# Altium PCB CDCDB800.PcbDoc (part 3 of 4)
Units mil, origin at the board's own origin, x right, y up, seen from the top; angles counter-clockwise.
Board outline 4100 x 4100 mil, 4 copper layers (Layer 1 - Top Layer, Layer 2 - GND, Layer 3 - PWR, Layer 4 - Bottom Layer), stack 61.2 mil thick; 245 components, 143 nets, 740 pads, 720 vias.
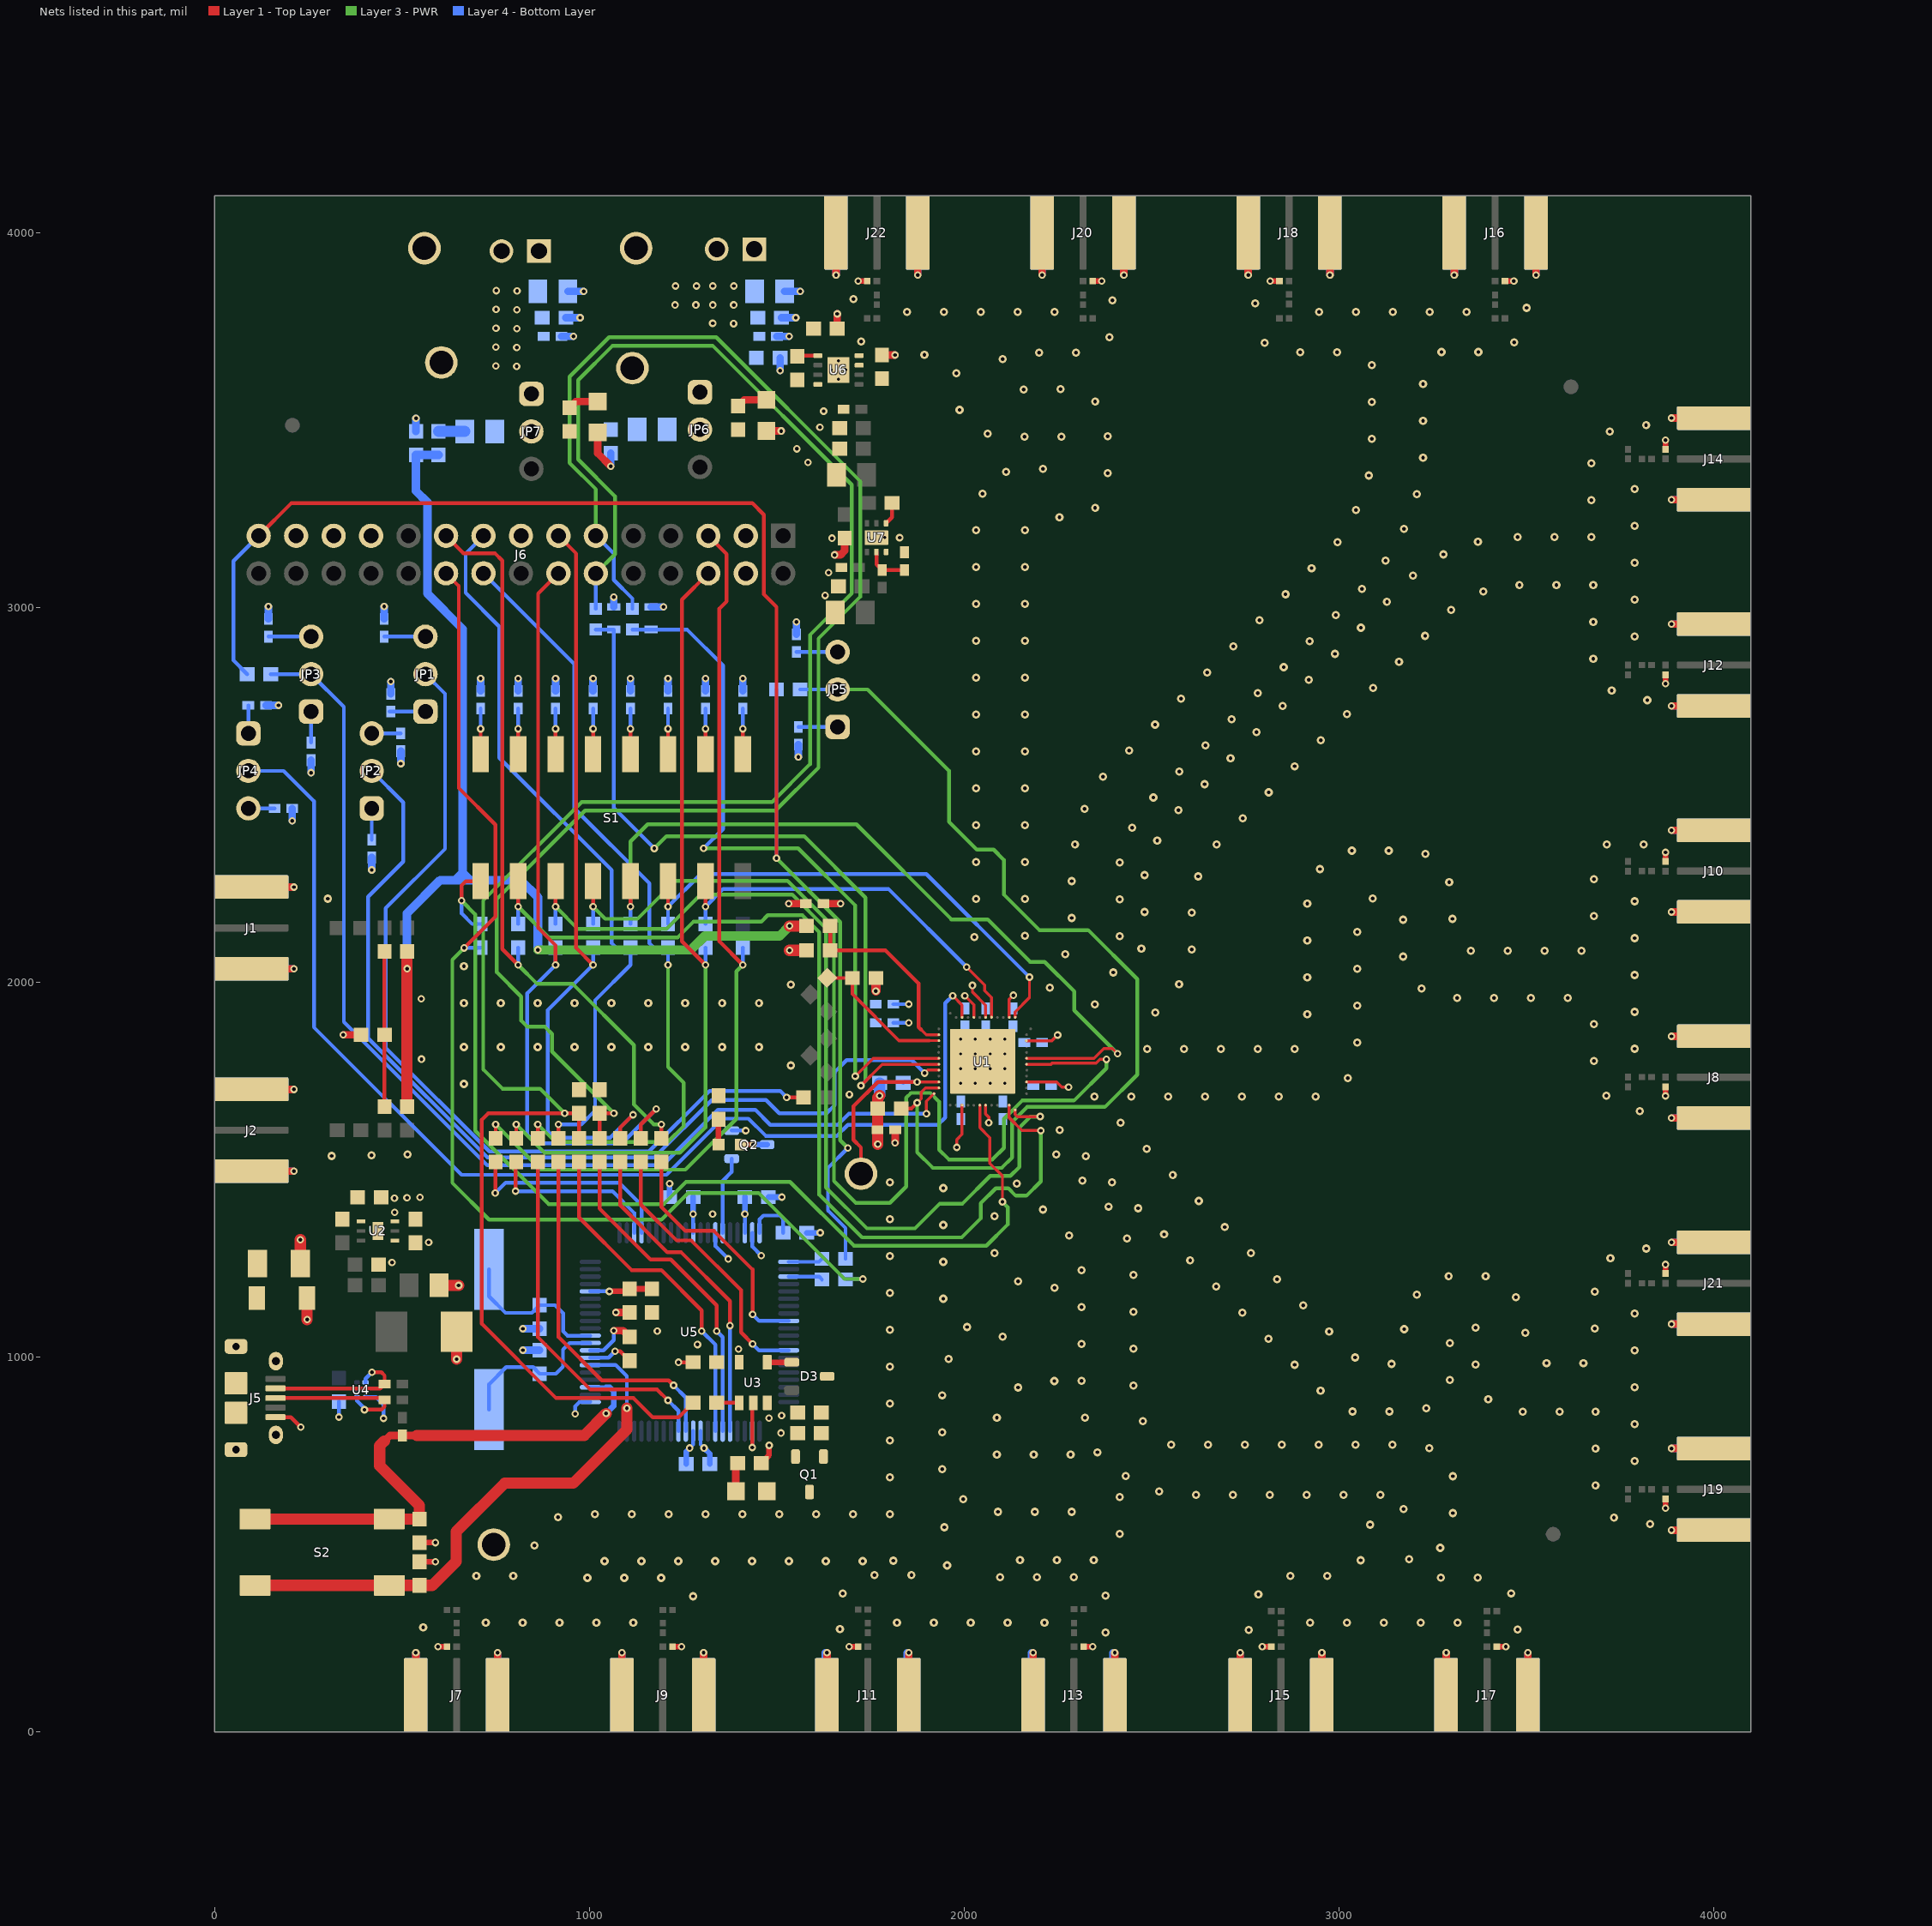
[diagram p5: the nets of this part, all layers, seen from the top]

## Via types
v1: diameter 22, hole 10, Layer 1 - Top Layer to Layer 4 - Bottom Layer, tented top, 430 vias
v2: diameter 20, hole 10, Layer 1 - Top Layer to Layer 4 - Bottom Layer, tented top, 268 vias
v3: diameter 19.68, hole 7.87, Layer 1 - Top Layer to Layer 4 - Bottom Layer, 22 vias

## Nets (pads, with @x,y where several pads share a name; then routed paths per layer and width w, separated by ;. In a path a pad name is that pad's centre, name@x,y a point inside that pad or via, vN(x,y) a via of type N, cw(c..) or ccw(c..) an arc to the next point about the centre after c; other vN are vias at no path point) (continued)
GND: C1.2 C2.2 C3.2 C4.2 C5.2 C6.2 C7.2 C8.2 C9.2 C10.2 C11.2 C12.2 C13.2 C14.2 C15.2 C16.2 C17.2 C18.2 C19.2 C20.2 C21.1 C22.2 C23.2 C24.1 C25.2 C26.2 C27.2 C28.2 C29.2 C30.2 C31.2 C32.2 C33.2 C34.2 C35.2 C36.2 C37.2 C38.2 C39.2 C40.2 C41.2 C42.2 C43.2 C44.2 C45.2 C46.2 C47.2 C48.2 D1.2 D5.2 D6.2 J1.2 J1.3 J1.4 J1.5 J2.2 J2.3 J2.4 J2.5 J3.2 J4.2 J5.5 J6.3 J6.4 J6.15 J6.23 J6.25 J6.27 J7.2 J7.3 J7.4 J7.5 J8.2 J8.3 J8.4 J8.5 J9.2 J9.3 J9.4 J9.5 J10.2 J10.3 J10.4 J10.5 J11.2 J11.3 J11.4 J11.5 J12.2 J12.3 J12.4 J12.5 J13.2 J13.3 J13.4 J13.5 J14.2 J14.3 J14.4 J14.5 J15.2 J15.3 J15.4 J15.5 J16.2 J16.3 J16.4 J16.5 J17.2 J17.3 J17.4 J17.5 J18.2 J18.3 J18.4 J18.5 J19.2 J19.3 J19.4 J19.5 J20.2 J20.3 J20.4 J20.5 J21.2 J21.3 J21.4 J21.5 J22.2 J22.3 J22.4 J22.5 Q1.2 Q2.2 R4.1 R5.1 R13.1 R26.1 R28.2 R29.2 R34.2 R55.1 R56.1 R57.2 R77.1 R78.1 R81.2 R82.2 R89.1 R90.1 R93.2 R94.2 R101.1 R102.1 R104.2 R106.2 R113.1 R114.1 R117.2 R118.2 R125.1 TP4.1 TP6.1 U1.49 U2.3 U2.7 U3.3 U4.3 U5.14 U5.19 U5.49 U5.61 U5.68 U6.4 U6.9 U7.3 U7.7@1766.5,3187.61 | length 10933.4
  Layer 1 - Top Layer w10.1: J5.5@162.4,840.04 203.66,840.04 v2(230.1,813.6) ; v2(1237.93,986.73) C19.2@1277.01,986.73
  Layer 1 - Top Layer w15: C22.2@546.78,454.16 v2(589.26,454.16) ; R55.1@546.78,505.34 v2(589.26,505.34) ; v2(596,227.6) R77.1@620.05,227.6 ; R81.2@1222.02,227.6 v2(1246.08,227.6) ; v2(1693.46,227.6) R89.1@1717.52,227.6 ; v2(1717.56,3872.4) R118.2@1741.61,3872.4 ; R93.2@2319.49,227.6 v2(2343.54,227.6) ; R114.1@2343.58,3872.4 v2(2367.64,3872.4) ; v2(2796,227.6) R101.1@2820.05,227.6 ; v2(2817.56,3872.4) R106.2@2841.61,3872.4 ; R104.2@3422.02,227.6 v2(3446.08,227.6) ; R102.1@3443.58,3872.4 v2(3467.64,3872.4) ; v2(3872.4,597.56) R113.1@3872.4,621.61 ; R117.2@3872.4,1223.58 v2(3872.4,1247.64) ; v2(3872.4,1697.56) R78.1@3872.4,1721.61 ; R82.2@3872.4,2323.58 v2(3872.4,2347.64) ; v2(3872.4,2797.56) R90.1@3872.4,2821.61 ; R94.2@3872.4,3423.58 v2(3872.4,3447.64)
  Layer 1 - Top Layer w20: J2.2@98.42,1496.79 v2(211.85,1496.79) ; J2.3@98.42,1714.9 v2(211.85,1714.9) ; J1.2@98.42,2036.79 v2(211.85,2036.79) ; J1.3@98.42,2254.9 v2(211.85,2254.9) ; v2(343.5,1860.85) R13.1@390.51,1860.85 ; J7.3@536.98,98.43 v2(536.98,211.85) ; J7.2@755.09,98.43 v2(755.09,211.85) ; D5.2@1022.4,3468.01 1022.4,3412.81 v2(1057.4,3377.81) ; v2(1065.3,1071.1) 1090.4,1071.1 C28.2@1107.4,1054.09 ; v2(1070.79,1119.61) C27.2@1107.4,1119.61 ; J9.3@1086.98,98.43 v2(1086.98,211.85) ; J9.2@1305.09,98.43 v2(1305.09,211.85) ; D6.2@1472.4,3472.56 v2@1512.09,3472.56 ; C15.2@1625.12,2211.02 v2(1670.74,2211.02) ; J11.3@1634.45,98.43 v2(1634.45,211.85) ; v2(1654.4,3141.5) 1670.6,3141.5 1681.5,3152.4 C42.2@1681.5,3186.11 ; v2(1658.54,3888.15) J22.2@1658.54,4001.57 ; C33.2@1661.5,3745 v2@1661.5,3784.69 ; C38.2@1781,3675 v2(1816,3675) ; v2@1816.5,1572.6 C12.2@1816.5,1607.13 ; J11.2@1852.56,98.43 v2(1852.56,211.85) ; v2(1876.65,3888.15) J22.3@1876.65,4001.57 ; J13.3@2184.45,98.43 v2(2184.45,211.85) ; v2(2208.54,3888.15) J20.2@2208.54,4001.57 ; J13.2@2402.56,98.43 v2(2402.56,211.85) ; v2(2426.65,3888.15) J20.3@2426.65,4001.57 ; J15.3@2736.98,98.43 v2(2736.98,211.85) ; v2(2758.54,3888.15) J18.2@2758.54,4001.57 ; J15.2@2955.09,98.43 v2(2955.09,211.85) ; v2(2976.65,3888.15) J18.3@2976.65,4001.57 ; J17.3@3286.98,98.43 v2(3286.98,211.85) ; v2(3308.54,3888.15) J16.2@3308.54,4001.57 ; J17.2@3505.09,98.43 v2(3505.09,211.85) ; v2(3526.65,3888.15) J16.3@3526.65,4001.57 ; v2(3888.15,538.54) J19.3@4001.57,538.54 ; v2(3888.15,756.65) J19.2@4001.57,756.65 ; v2(3888.15,1088.54) J21.3@4001.57,1088.54 ; v2(3888.15,1306.65) J21.2@4001.57,1306.65 ; v2(3888.15,1638.54) J8.3@4001.57,1638.54 ; v2(3888.15,1856.65) J8.2@4001.57,1856.65 ; v2(3888.15,2188.54) J10.3@4001.57,2188.54 ; v2(3888.15,2406.65) J10.2@4001.57,2406.65 ; v2(3888.15,2738.54) J12.3@4001.57,2738.54 ; v2(3888.15,2956.65) J12.2@4001.57,2956.65 ; v2(3888.15,3288.54) J14.3@4001.57,3288.54 ; v2(3888.15,3506.65) J14.2@4001.57,3506.65
  Layer 1 - Top Layer w30: R57.2@228.86,1250.36 v2(228.86,1313.76) ; v2(246.95,1100.85) C24.1@246.95,1158.44 ; C16.2@598.78,1192.11 v2@651.81,1192.11 ; v2@645.79,994.9 D1.2@645.79,1068.29 ; v2(1534.26,2086.02) R26.1@1579.88,2086.02
  Layer 4 - Bottom Layer w10.1: v2(331.78,840.38) C21.1@331.78,881.8 ; U4.3@403.59,893.61 431.19,893.61 450.6,874.2 v2(450.6,836.9) ; v2(962.1,849.1) 962.1,869.1 973.59,880.59 U5.61@1002.64,880.59 ; U5.68@1002.64,1018.39 1037.89,1018.39 1065.3,1045.8 v2(1065.3,1071.1) ; U5.49@1296.93,802.84 1296.93,767.25 v2(1306.3,757.87) ; U5.14@1336.3,1332.36 1336.3,1296.9 v2(1370.7,1262.5) ; Q2.2@1380.16,1605 v2(1417.4,1605) ; U5.19@1434.73,1332.36 1434.73,1295.77 v2(1459,1271.5) ; C11.2@1811.5,1892.53 v2(1852.73,1892.53) ; C10.2@1811.5,1942.53 v2(1852.73,1942.53)
  Layer 4 - Bottom Layer w15: C30.2@1214.41,1427.6 v2(1214.41,1463.41) ; v2(1306.3,757.87) 1321.5,742.68 C32.2@1321.5,715 ; C31.2@1478.03,1427.44 v2(1513.84,1427.44) ; C29.2@1580.39,1332.36 v2(1616.2,1332.36)
  Layer 4 - Bottom Layer w20: J2.4@98.42,1496.79 v2(211.85,1496.79) ; J2.5@98.42,1714.9 v2(211.85,1714.9) ; J1.4@98.42,2036.79 v2(211.85,2036.79) ; J1.5@98.42,2254.9 v2(211.85,2254.9) ; R28.2@143.5,2970.49 v2(143.5,3003.7) ; v2(207.24,2431.79) R29.2@207.24,2465 ; R4.1@452.6,2970.49 v2(452.6,3003.7) ; v2(496.89,2584.55) R5.1@496.89,2617.76 ; J7.5@536.98,98.43 v2(536.98,211.85) ; C9.2@537.4,3471.01 v2(537.4,3506.22) ; J7.4@755.09,98.43 v2(755.09,211.85) ; v2(822.8,1019.09) C25.2@867.4,1019.09 ; v2(822.8,1076.1) C26.2@867.4,1076.1 ; C48.2@925.5,3724.91 v2(957.91,3724.91) ; C47.2@937.38,3774.41 v2(975.59,3774.41) ; C46.2@942.88,3845.12 v2(984.88,3845.12) ; v2(1057.4,3377.81) C1.2@1057.4,3413.02 ; C14.2@1065,3002.44 v2(1065,3028.6) ; J9.5@1086.98,98.43 v2(1086.98,211.85) ; C13.2@1165,3002.44 v2(1198.21,3002.44) ; J9.4@1305.09,98.43 v2(1305.09,211.85) ; C41.2@1500.88,3724.91 v2(1533.29,3724.91) ; C40.2@1512.76,3774.41 v2(1550.97,3774.41) ; C39.2@1521.26,3845.12 v2(1563.26,3845.12) ; R34.2@1552.91,2929.65 v2(1552.91,2962.86) ; J11.5@1629.85,98.43 v2@1629.85,211.85 ; v2(1658.54,3888.15) J22.4@1658.54,4001.57 ; J11.4@1847.96,98.43 v2@1847.96,211.85 ; v2(1876.65,3888.15) J22.5@1876.65,4001.57 ; J13.5@2179.85,98.43 v2@2179.85,211.85 ; v2(2208.54,3888.15) J20.4@2208.54,4001.57 ; J13.4@2397.96,98.43 v2@2397.96,211.85 ; v2(2426.65,3888.15) J20.5@2426.65,4001.57 ; J15.5@2736.98,98.43 v2(2736.98,211.85) ; v2(2758.54,3888.15) J18.4@2758.54,4001.57 ; J15.4@2955.09,98.43 v2(2955.09,211.85) ; v2(2976.65,3888.15) J18.5@2976.65,4001.57 ; J17.5@3286.98,98.43 v2(3286.98,211.85) ; v2(3308.54,3888.15) J16.4@3308.54,4001.57 ; J17.4@3505.09,98.43 v2(3505.09,211.85) ; v2(3526.65,3888.15) J16.5@3526.65,4001.57 ; v2(3888.15,538.54) J19.5@4001.57,538.54 ; v2(3888.15,756.65) J19.4@4001.57,756.65 ; v2(3888.15,1088.54) J21.5@4001.57,1088.54 ; v2(3888.15,1306.65) J21.4@4001.57,1306.65 ; v2(3888.15,1638.54) J8.5@4001.57,1638.54 ; v2(3888.15,1856.65) J8.4@4001.57,1856.65 ; v2(3888.15,2188.54) J10.5@4001.57,2188.54 ; v2(3888.15,2406.65) J10.4@4001.57,2406.65 ; v2(3888.15,2738.54) J12.5@4001.57,2738.54 ; v2(3888.15,2956.65) J12.4@4001.57,2956.65 ; v2(3888.15,3288.54) J14.5@4001.57,3288.54 ; v2(3888.15,3506.65) J14.4@4001.57,3506.65
  other v1: 2378.13,265.65 2760.23,272.37 3477.62,273.05 1668.84,274.49 556.64,279.49 723.63,292.04 822.05,292.04 920.48,292.05 1018.9,292.05 1117.33,292.05 1821.09,292.04 1919.52,292.04 2017.94,292.05 2116.37,292.05 2214.79,292.05 2923.63,292.04 3022.05,292.04 3120.48,292.05 3218.9,292.05 3317.33,292.05 1277.01,362.19 2378.13,364.08 2785.71,367.44 1676.24,369.77 3460.53,369.98 994.92,411.4 1093.35,411.4 1191.77,411.4 3272.9,411.57 3371.33,411.58 2096.04,413.29 2194.46,413.29 2292.89,413.29 698.44,416.79 796.87,416.79 2870.95,416.66 2969.37,416.66 1761.48,418.98 1859.9,418.98 1954.97,444.46 1040.63,455.82 1139.05,455.83 1237.48,455.83 1335.9,455.83 1434.33,455.83 1532.75,455.83 1631.18,455.83 1729.6,455.83 1811.5,457.1 3058.57,458.25 2149.48,458.98 2247.9,458.98 2346.33,458.98 3187.66,460.79 3271.09,491.5 853.32,497.42 2415.93,528.58 1947.8,546.4 3084.05,553.33 3831.54,555.31 3734.61,572.4 916.59,572.82 1014.64,581.4 1113.06,581.4 1211.49,581.4 1309.91,581.4 1408.34,581.4 1506.76,581.4 1605.19,581.4 1703.61,581.4 1802.04,581.4 3304.76,583.99 2090.56,587.51 2188.98,587.51 2287.41,587.51 3173.25,594.92 1998.07,621.17 2415.92,627 2619.08,633.01 2717.51,633.01 2815.93,633.01 2914.36,633.01 3012.78,633.01 3111.21,633.01 2521.03,641.59 3685.39,657.64 1802.03,679.83 3304.76,682.42 2431.83,683.18 1941.61,701.8 3790.03,723.43 2087.85,740.47 2186.27,740.47 2284.7,740.47 2356.43,746.45 3685.39,756.06 3241.49,757.81 2552.89,766.39 2651.31,766.39 2749.74,766.39 2848.16,766.39 2946.59,766.39 3045.01,766.39 3143.44,766.39 1802.03,778.25 1941.61,800.22 3790.03,821.85 2477.49,829.66 2087.85,838.89 2322.76,838.94 3491.54,854.49 3589.97,854.49 3685.39,854.49 3036.95,855.26 3135.38,855.26 3233.43,863.84 1802.03,876.68 3399.05,888.15 1941.61,898.65 2951.71,910.47 2144.3,919.52 3790.03,920.27 2452.01,924.73 2241.23,936.61 2314.19,936.99 3296.69,939.24 1802.03,975.1 2882.12,980.07 3365.39,980.64 3141.2,982.44 3554.74,984.48 3653.16,984.48 1958.7,995.58 3044.27,999.53 3790.03,1018.7 2452.01,1023.15 2314.18,1035.41 3296.69,1037.66 2812.52,1049.67 2102.98,1055.34 3498.28,1065.11 2974.67,1069.13 1802.03,1073.53 3174.86,1074.93 3683.83,1076.97 3365.39,1079.06 2007.91,1080.82 3790.03,1117.12 2742.92,1119.26 2452.01,1121.58 2314.18,1133.84 2905.07,1138.73 1944.64,1156.21 3472.81,1160.18 3208.52,1167.42 1802.03,1171.95 3683.83,1175.4 2241.3,1185.76 2673.33,1188.86 2144.37,1202.85 2835.48,1208.32 3293.76,1216.63 3392.19,1216.63 2452.01,1220 2314.18,1232.26 1944.64,1254.64 2603.73,1258.46 3725.42,1264.6 1802.03,1270.38 2081.1,1278.25 2765.88,1277.92 3820.49,1290.08 2434.92,1316.93 2280.52,1324.75 2534.13,1328.05 2696.28,1347.52 1944.64,1353.06 1802.03,1368.8 2081.1,1376.68 2210.92,1394.35 2464.54,1397.65 2385.71,1402.17 2626.69,1417.11 1944.64,1451.49 2141.33,1463.95 1802.03,1467.23 2394.94,1467.25 2316.11,1471.77 2557.09,1486.71 312.3,1537.3 2325.34,1536.84 418.8,1539.3 2246.51,1541.36 514.7,1541.6 2487.49,1556.31 2255.75,1606.44 2417.9,1625.9 3803.8,1656.56 2348.3,1695.5 2446.72,1695.5 2545.15,1695.5 2643.57,1695.5 2742,1695.5 2840.42,1695.5 2938.85,1695.5 3714.6,1698.16 665.4,1729.57 3024.09,1744.71 1538.03,1778.78 3680.93,1790.65 2488.94,1822.71 2587.36,1822.71 2685.79,1822.71 2784.21,1822.71 2882.64,1822.71 3790.03,1823.43 665.4,1827.99 763.82,1827.99 862.25,1827.99 960.67,1827.99 1059.1,1827.99 1157.52,1827.99 1255.95,1827.99 1354.37,1827.99 1452.8,1827.99 3049.56,1839.78 3680.93,1889.07 2916.3,1915.2 2510.81,1920.14 3790.03,1921.85 3049.56,1938.21 2348.9,1941.8 665.4,1945 763.82,1945 862.25,1945 960.67,1945 1059.1,1945 1157.52,1945 1255.95,1945 1354.37,1945 1452.8,1945 3316.06,1958.67 3414.49,1958.67 3512.91,1958.67 3611.34,1958.67 3220.99,1984.14 2228.9,1986.4 1538.03,1994.21 2574.07,1995.53 2916.3,2013.63 3790.03,2020.27 2398.11,2027.04 3049.56,2036.63 665.4,2043.42 3171.78,2069.38 2270.5,2075.6 3352.73,2084.91 3451.16,2084.91 3549.58,2084.91 3648.01,2084.91 2607.74,2088.02 2473.51,2090.3 2916.3,2112.05 3790.03,2118.7 2028.1,2121.2 2415.2,2123.97 2162.39,2125.2 3049.56,2135.06 3171.78,2167.81 3303.52,2170.15 2287.59,2172.53 3681.67,2177.4 2607.74,2186.45 2482.09,2188.35 2916.3,2210.48 3790.03,2217.12 2415.2,2222.39 301.6,2223.9 2032.1,2223.63 2162.39,2223.63 3091.16,2224.26 3294.94,2268.2 2287.59,2270.96 3681.67,2275.83 2624.83,2283.38 2482.09,2286.78 2949.96,2302.96 2415.2,2320.82 2032.1,2322.05 2162.39,2322.05 3231.68,2343.6 3035.2,2352.18 3133.63,2352.18 3715.33,2368.32 3813.76,2368.32 2296.17,2369.01 2674.04,2368.61 2515.75,2379.27 2448.87,2413.31 2032.1,2420.48 2162.39,2420.48 2743.64,2438.21 2572.21,2459.89 2321.64,2464.08 2505.32,2493.93 2813.23,2507.81 2032.1,2518.9 2162.39,2518.9 2641.8,2529.49 2370.85,2549.32 2574.92,2563.53 2882.83,2577.4 2711.4,2599.09 2032.1,2617.33 2162.39,2617.33 2440.45,2618.92 2644.52,2633.13 2952.43,2647 2780.99,2668.68 2510.05,2688.51 2714.11,2702.72 2032.1,2715.75 2162.39,2715.75 3022.02,2716.6 2850.59,2738.28 3823.71,2753.73 2579.64,2758.11 2783.71,2772.32 3728.64,2779.2 3091.62,2786.19 2920.19,2807.88 2032.1,2814.18 2162.39,2814.18 2649.24,2827.71 2853.31,2841.92 3161.22,2855.79 3679.43,2864.44 2989.78,2877.47 2718.84,2897.3 2922.9,2911.51 2032.1,2912.6 2162.39,2912.6 3790.03,2923.43 3230.81,2925.39 3059.38,2947.07 3679.43,2962.86 2788.44,2966.9 2992.5,2981.11 3300.41,2994.99 2032.1,3011.03 2162.39,3011.03 3128.98,3016.67 3790.03,3021.85 2858.03,3036.5 3385.65,3044.2 3062.1,3050.71 3482.58,3061.29 3581,3061.29 3679.43,3061.29 3198.57,3086.26 2927.63,3106.1 2032.1,3109.45 2162.39,3109.45 3790.03,3120.27 3125.36,3126.11 3279.2,3142.72 2997.23,3175.69 3371.69,3176.38 3477.45,3188.88 3575.87,3188.88 3674.3,3188.88 2032.1,3207.88 2162.39,3207.88 3174.58,3211.34 3790.03,3218.7 2254.88,3241.54 3046.44,3260.93 2349.95,3267.01 3674.3,3287.3 3208.24,3303.83 2049.19,3304.81 3790.03,3317.12 3080.1,3353.42 2383.61,3359.5 2112.73,3362.76 2210.78,3371.34 3674.3,3385.73 3225.33,3400.76 3088.68,3451.47 2161.56,3456.57 2259.99,3456.57 2383.61,3457.93 2063.51,3465.15 3723.51,3470.97 3820.44,3488.06 3225.33,3499.19 1988.12,3528.42 2349.95,3550.42 3088.68,3549.9 2159.68,3583.2 2257.46,3584.08 3225.33,3597.61 1979.54,3626.47 3088.68,3648.32 2103.22,3663.82 1894.3,3675.68 2200.15,3680.92 2298.58,3680.92 2897.77,3681.98 2996.19,3681.98 3274.54,3682.85 3372.97,3682.85 2802.7,3707.46 3468.04,3708.32 1725.21,3711.33 2387.78,3722.51 1848.07,3790.03 1946.5,3790.03 2044.92,3790.03 2143.35,3790.03 2241.77,3790.03 2948.07,3790.03 3046.5,3790.03 3144.92,3790.03 3243.35,3790.03 3341.77,3790.03 3501.7,3800.81 2777.5,3812.6 2396.36,3820.56 1705.11,3823.93
  other v2: 1511.7,797.9 1479.8,837.8 1513.3,844.2 645.9,994.9 651.41,1191.71 473.3,1252.9 480.4,1386.6 480,1424.4 513.4,1425.7 548.3,1426.7 1816.1,1572.2 1694,1701.2 552.1,1795.8 551.7,1956.7 1629.7,3033.21 1638.6,3094.31 1647.8,3186.11 1828.15,3187.61 1583.9,3388.3 1553.9,3424.6 1512.09,3472.17 1615.4,3482.3 1625.5,3525.2 1661.88,3784.69
  other v3: 1990.94,1730.94 2030.31,1730.94 2069.68,1730.94 2109.06,1730.94 1990.94,1770.31 2030.31,1770.31 2069.68,1770.31 2109.06,1770.31 1990.94,1809.68 2030.31,1809.68 2069.68,1809.68 2109.06,1809.68 1990.94,1849.06 2030.31,1849.06 2069.68,1849.06 2109.06,1849.06 1744.84,3187.61 1788.15,3187.61 1665,3610.39 1645.32,3635 1684.68,3635 1665,3659.61
GPIO2: J6.13 R39.1 R64.2 | length 2060.7
  Layer 1 - Top Layer w10.1: J6.13@917.6,3192.4 965,3145 965,2092.32 v2(1010,2047.32) ; R64.2@1082.4,1584.09 1082.4,1613.1 v2(1116.6,1647.3)
  Layer 4 - Bottom Layer w10.1: R39.1@1010,2093.5 v2(1010,2047.32) 889,1926.32 889,1603.8 906.6,1586.2 1055.5,1586.2 v2(1116.6,1647.3)
GPIO3: J6.14 R37.1 R61.2 | length 2104
  Layer 1 - Top Layer w10.1: v2(910,2047.32) 910,2099.3 863.3,2146 863.3,3038.1 J6.14@917.6,3092.4 ; R61.2@1137.4,1584.09 1137.4,1621.6 v2(1178.3,1662.5)
  Layer 4 - Bottom Layer w10.1: R37.1@910,2093.5 v2(910,2047.32) 834.5,1971.82 834.5,1594.3 857.7,1571.1 1086.9,1571.1 v2(1178.3,1662.5)
GPIO4: J6.17 R41.1 R67.2 | length 1948.3
  Layer 1 - Top Layer w10.1: R67.2@917.4,1584.09 v2(917.4,1621.6)
  Layer 4 - Bottom Layer w10.1: J6.17@717.6,3192.4 670,3144.8 670,3040.3 760,2950.3 760,2600 1060,2300 1060,2105 1071.5,2093.5 R41.1@1110,2093.5 1110,2047.32 1015.5,1952.82 1015.5,1658.7 978.4,1621.6 v2(917.4,1621.6)
GPIO5: J6.18 R43.1 R68.2 | length 2183.2
  Layer 1 - Top Layer w10.1: R68.2@862.4,1584.09 v2(862.4,1621.6)
  Layer 3 - PWR w10.1: v2(862.4,1621.6) 909.05,1574.95 1209.75,1574.95 1252.2,1617.4 1252.2,1732.4 1210,1774.6 v2(1210,2047.32)
  Layer 4 - Bottom Layer w10.1: J6.18@717.6,3092.4 960,2850 960,2465 1160,2265 1160,2105 1171.5,2093.5 R43.1@1210,2093.5 v2(1210,2047.32)
GPIO6: J6.19 R35.1 R59.2 | length 2009.4
  Layer 1 - Top Layer w10.1: J6.19@617.6,3192.4 663.9,3146.1 748,3146.1 767.6,3126.5 767.6,2089.72 v2(810,2047.32) ; R59.2@1192.4,1584.09 v2(1192.4,1621.6)
  Layer 3 - PWR w10.1: v2(810,2047.32) 860.92,1996.4 955.9,1996.4 1119,1833.3 1119,1674.7 1172.1,1621.6 v2(1192.4,1621.6)
  Layer 4 - Bottom Layer w10.1: v2(810,2047.32) R35.1@810,2093.5
GPIO7: J6.20 R32.1 R60.1 | length 3078.4
  Layer 1 - Top Layer w10.1: J6.20@617.6,3092.4 651.6,3058.4 651.6,2519.1 749.6,2421.1 749.6,2176 v2(666.1,2092.5)
  Layer 3 - PWR w10.1: v2(666.1,2092.5) 634.4,2060.8 634.4,1465.4 732.2,1367.6 1192.7,1367.6 1263,1437.9 1452.4,1437.9 1681.3,1209 v2(1730.4,1209)
  Layer 4 - Bottom Layer w10.1: v2(666.1,2092.5) 709,2092.5 R32.1@710,2093.5 ; R60.1@1686.2,1209 v2(1730.4,1209)
GPIO8: J6.5 R47.1 R70.2 | length 2450.1
  Layer 1 - Top Layer w10.1: R70.2@750,1584.09 v2(750,1621.6) ; J6.5@1317.6,3192.4 1366.7,3143.3 1366.7,3017.4 1347.2,2997.9 1347.2,2110.12 v2(1410,2047.32)
  Layer 3 - PWR w10.1: v2(750,1621.6) 870.95,1500.65 1256.55,1500.65 1392.4,1636.5 1392.4,2029.72 v2(1410,2047.32)
  Layer 4 - Bottom Layer w10.1: v2(1410,2047.32) R47.1@1410,2093.5
GPIO9: J6.6 R45.1 R69.2 | length 2182.1
  Layer 1 - Top Layer w10.1: R69.2@805,1584.09 v2(805,1621.6) ; v2(1310,2047.32) 1247.3,2110.02 1247.3,3022.1 J6.6@1317.6,3092.4
  Layer 3 - PWR w10.1: v2(805,1621.6) 881.05,1545.55 1241.65,1545.55 1310,1613.9 v2(1310,2047.32)
  Layer 4 - Bottom Layer w10.1: v2(1310,2047.32) R45.1@1310,2093.5
GPIO12: J6.29 R27.1 R31.1 R58.1 | length 4381.3
  Layer 1 - Top Layer w10.1: J6.29@117.6,3192.4 205.2,3280 1435,3280 1466.1,3248.9 1466.1,3036.4 1499.61,3002.89 v2(1499.61,2331.81)
  Layer 3 - PWR w10.1: v2(1499.61,2331.81) 1669.8,2161.61 1669.8,1578.8 v2(1690.1,1558.5)
  Layer 4 - Bottom Layer w10.1: R27.1@87.01,2823.25 50,2860.26 50,3124.8 J6.29@117.6,3192.4 ; v2(1499.61,2331.81) R31.1@1499.61,2782.4 ; R58.1@1683.9,1262.6 1683.9,1344.9 1636.9,1391.9 1636.9,1505.3 v2(1690.1,1558.5)
I2CPU: U3.2 U5.42 | length 163.7
  Layer 1 - Top Layer w10.1: v2(1434.73,759.27) 1434.73,875.59 U3.2@1437.6,878.46
  Layer 4 - Bottom Layer w10.1: v2@1434.73,759.5 U5.42@1434.73,802.84
NetC20_1: C20.1 R49.1 U2.4
NetC23_1: C23.1 D3.3 Q1.1 R56.2
NetC25_1: C25.1 U5.69 Y1.1 | length 424.1
  Layer 4 - Bottom Layer w10.1: Y1.1@732.4,860.59 732.4,927.6 778.3,973.5 850,973.5 C25.1@867.4,956.1 910.6,956.1 929.6,975.1 929.6,1020.7 946.97,1038.07 U5.69@1002.64,1038.07
NetC26_1: C26.1 U5.70 Y1.2 | length 431
  Layer 4 - Bottom Layer w10.1: Y1.2@732.4,1234.61 732.4,1162.4 776.3,1118.5 846.81,1118.5 C26.1@867.4,1139.09 908.51,1139.09 930.2,1117.4 930.2,1069.4 941.84,1057.76 U5.70@1002.64,1057.76
NetC27_1: C27.1 R72.1 U5.76 | length 167.6
  Layer 1 - Top Layer w15: v2(1053.5,1175.87) 1100.67,1175.87 C27.1@1107.4,1182.6 R72.1@1167.4,1182.6
  Layer 4 - Bottom Layer w10.1: U5.76@1002.64,1175.87 v2(1053.5,1175.87)
NetC28_1: C28.1 U5.67 | length 122.4
  Layer 1 - Top Layer w10.1: v2(1068.9,1016.2) 1082.3,1016.2 C28.1@1107.4,991.1
  Layer 4 - Bottom Layer w10.1: U5.67@1002.64,998.7 1051.4,998.7 v2(1068.9,1016.2)
NetC29_1: C29.1 U5.20 | length 143.7
  Layer 4 - Bottom Layer w10.1: U5.20@1454.41,1332.36 1454.41,1368.21 1464.5,1378.3 1508.5,1378.3 1517.4,1369.4 C29.1@1517.4,1332.36
NetC33_1: C33.1 R121.1 R122.1 U6.8 | length 34.4
  Layer 4 - Bottom Layer w20: v2(1509.09,3632.99) R121.1@1509.09,3667.4
NetC38_1: C38.1 U6.3
NetD2_1: D2.1 R51.1 | length 77
  Layer 1 - Top Layer w20: D2.1@1391.06,642.6 1391.06,712.76 R51.1@1395.91,717.6
NetD2_2: D2.2 Q1.3
NetD3_1: D3.1 U3.4 | length 65.4
  Layer 1 - Top Layer w15: U3.4@1475,986.73 D3.1@1540.35,986.73
NetD4_1: D4.1 R71.1 | length 67.4
  Layer 1 - Top Layer w15: D4.1@1345,1567.6 R71.1@1345,1635
NetD4_2: D4.2 Q2.3 | length 70.6
  Layer 1 - Top Layer w15: D4.2@1404.06,1567.6 v2(1437.4,1567.6)
  Layer 4 - Bottom Layer w15: v2(1437.4,1567.6) Q2.3@1474.65,1567.6
NetD5_1: D5.1 R126.1 | length 81.9
  Layer 1 - Top Layer w20: R126.1@947.4,3534 964.08,3550.69 D5.1@1022.4,3550.69
NetD6_1: D6.1 R127.1 | length 81.7
  Layer 1 - Top Layer w20: R127.1@1397.4,3539 1413.63,3555.24 D6.1@1472.4,3555.24
NetJP1_1: JP1.1 R2.1 | length 110
  Layer 4 - Bottom Layer w10.1: R2.1@467.1,2723.3 JP1.1@577.1,2723.3
NetJP1_3: JP1.3 R4.2 | length 110
  Layer 4 - Bottom Layer w10.1: R4.2@452.6,2923.25 JP1.3@562.6,2923.25
NetJP2_1: JP2.1 R3.1 | length 84
  Layer 4 - Bottom Layer w10.1: R3.1@419.29,2381.02 JP2.1@419.29,2465
NetJP2_3: JP2.3 R5.2 | length 77.6
  Layer 4 - Bottom Layer w10.1: JP2.3@419.29,2665 R5.2@496.89,2665
NetJP3_1: JP3.1 R24.1 | length 82.6
  Layer 4 - Bottom Layer w10.1: R24.1@257.6,2640.65 JP3.1@257.6,2723.25
NetJP3_3: JP3.3 R28.1 | length 114.1
  Layer 4 - Bottom Layer w10.1: R28.1@143.5,2923.25 JP3.3@257.6,2923.25
NetJP4_1: JP4.1 R25.1 | length 75
  Layer 4 - Bottom Layer w10.1: JP4.1@90,2665 R25.1@90,2740
NetJP4_3: JP4.3 R29.1 | length 70
  Layer 4 - Bottom Layer w10.1: JP4.3@90,2465 R29.1@160,2465
NetJP5_1: JP5.1 R30.1 | length 104.7
  Layer 4 - Bottom Layer w10.1: R30.1@1557.91,2682.4 JP5.1@1662.6,2682.4
NetJP5_3: JP5.3 R34.1 | length 109.7
  Layer 4 - Bottom Layer w10.1: R34.1@1552.91,2882.4 JP5.3@1662.6,2882.4
NetL2_2: L2.2 R1.1 | length 70
  Layer 4 - Bottom Layer w30: R1.1@597.4,3471.01 L2.2@667.4,3471.01
NetQ2_1: Q2.1 U5.15 | length 207.8
  Layer 4 - Bottom Layer w10.1: U5.15@1355.99,1332.36 1355.99,1470.59 1380.16,1494.76 Q2.1@1380.16,1530.2
NetR6_2: R6.2 TP1.1 U1.10 | length 481.4
  Layer 1 - Top Layer w7.87: v2(1875,1735) 1875.12,1734.88 U1.10@1932.87,1734.88
  Layer 1 - Top Layer w10.1: TP1.1@1725,1490 1725,1560 1705,1580 1705,1670 1770,1735 v2(1875,1735)
  Layer 4 - Bottom Layer w10.1: R6.2@1837.87,1732.13 1840.75,1735 v2(1875,1735)
NetR7_2: R7.2 R9.2 U1.3 | length 392.3
  Layer 1 - Top Layer w7.87: 1907.1,1845.12 U1.3@1932.87,1845.12
  Layer 1 - Top Layer w8.8: R9.2@1634.87,2012.29 R7.2@1701.81,2012.29 1701.81,1969.49 1826.18,1845.12 1907.1,1845.12
NetR12_2: R12.2 R13.2 R16.1 | length 414
  Layer 1 - Top Layer w10.1: R16.1@453.5,1668.84 R13.2@453.5,1860.85 R12.2@453.5,2082.85
NetR23_1: R23.1 R26.2 U1.2 | length 516.3
  Layer 1 - Top Layer w7.87: 1885.65,1874.35 1899.13,1860.87 U1.2@1932.87,1860.87
  Layer 1 - Top Layer w10.1: R23.1@1642.87,2151.02 R26.2@1642.87,2086.02 1790.18,2086.02 1878.5,1997.7 1878.5,1881.5 1885.65,1874.35
NetR33_2: R33.2 S1.16 | length 122.1
  Layer 1 - Top Layer w10.1: S1.16@710,2609.29 v2(710,2677.32)
  Layer 4 - Bottom Layer w10.1: v2(710,2677.32) R33.2@710,2731.38
NetR36_2: R36.2 S1.15 | length 122.1
  Layer 1 - Top Layer w10.1: S1.15@810,2609.29 v2(810,2677.32)
  Layer 4 - Bottom Layer w10.1: v2(810,2677.32) R36.2@810,2731.38
NetR38_2: R38.2 S1.14 | length 122.1
  Layer 1 - Top Layer w10.1: S1.14@910,2609.29 v2(910,2677.32)
  Layer 4 - Bottom Layer w10.1: v2(910,2677.32) R38.2@910,2731.38
NetR40_2: R40.2 S1.13 | length 122.1
  Layer 1 - Top Layer w10.1: S1.13@1010,2609.29 v2(1010,2677.32)
  Layer 4 - Bottom Layer w10.1: v2(1010,2677.32) R40.2@1010,2731.38
NetR42_2: R42.2 S1.12 | length 122.1
  Layer 1 - Top Layer w10.1: S1.12@1110,2609.29 v2(1110,2677.32)
  Layer 4 - Bottom Layer w10.1: v2(1110,2677.32) R42.2@1110,2731.38
NetR44_1: R44.1 S1.11 | length 122.1
  Layer 1 - Top Layer w10.1: S1.11@1210,2609.29 v2(1210,2677.32)
  Layer 4 - Bottom Layer w10.1: v2(1210,2677.32) R44.1@1210,2731.38
NetR46_1: R46.1 S1.10 | length 122.1
  Layer 1 - Top Layer w10.1: S1.10@1310,2609.29 v2(1310,2677.32)
  Layer 4 - Bottom Layer w10.1: v2(1310,2677.32) R46.1@1310,2731.38
NetR48_1: R48.1 S1.9 | length 122.1
  Layer 1 - Top Layer w10.1: S1.9@1410,2609.29 v2(1410,2677.32)
  Layer 4 - Bottom Layer w10.1: v2(1410,2677.32) R48.1@1410,2731.38
NetR54_2: R54.2 U3.1 | length 60.2
  Layer 1 - Top Layer w10.1: R54.2@1340,878.46 U3.1@1400.2,878.46
NetR58_2: R58.2 U5.21 | length 92.1
  Layer 4 - Bottom Layer w10.1: U5.21@1532.17,1254.61 1612.91,1254.61 R58.2@1620.91,1262.6
NetR59_1: R59.1 U5.29 | length 656.9
  Layer 1 - Top Layer w10.1: R59.1@1192.4,1521.1 1192.4,1401.1 1256.3,1337.2 1332.7,1337.2 1435.67,1234.23 v2(1435.67,1114.33)
  Layer 4 - Bottom Layer w10.1: v2@1435,1115 v2(1435.67,1114.33) 1452.87,1097.13 U5.29@1532.17,1097.13
NetR60_2: R60.2 U5.23 | length 91.9
  Layer 4 - Bottom Layer w10.1: U5.23@1532.17,1215.24 1613.27,1215.24 R60.2@1620.91,1207.6
NetR61_1: R61.1 U5.33 | length 736.5
  Layer 1 - Top Layer w10.1: R61.1@1137.4,1521.1 1137.4,1407.7 1233.1,1312 1272.1,1312 1405,1179.1 1405,1066.26 v2(1435.67,1035.59)
  Layer 4 - Bottom Layer w10.1: v2@1435,1036.26 v2(1435.67,1035.59) 1452.87,1018.39 U5.33@1532.17,1018.39
NetR64_1: R64.1 U5.45 | length 861.4
  Layer 1 - Top Layer w10.1: R64.1@1082.4,1521.1 1082.4,1406.1 1208.4,1280.1 1245.4,1280.1 1375.67,1149.83 v2(1375.67,1084.33)
  Layer 4 - Bottom Layer w10.1: U5.45@1375.67,802.84 v2(1375.67,1084.33)
NetR65_1: R65.1 U5.46 | length 886.2
  Layer 1 - Top Layer w10.1: R65.1@1027.4,1521.1 1027.4,1396.7 1163.3,1260.8 1217.7,1260.8 1340,1138.5 v2(1340,1070)
  Layer 4 - Bottom Layer w10.1: v2(1340,1070) 1355.99,1054.01 U5.46@1355.99,802.84
NetR66_1: R66.1 U5.47 | length 915.6
  Layer 1 - Top Layer w10.1: R66.1@972.4,1521.1 972.4,1373 1112.7,1232.7 1192.3,1232.7 1300,1125 v2(1300,1070)
  Layer 4 - Bottom Layer w10.1: v2(1300,1070) 1336.3,1033.7 U5.47@1336.3,802.84
NetR67_1: R67.1 U5.51 | length 963.7
  Layer 1 - Top Layer w10.1: R67.1@917.4,1521.1 917.4,1054.2 1033.4,938.2 1211.8,938.2 v2(1225,925)
  Layer 4 - Bottom Layer w10.1: v2(1225,925) 1257.56,892.44 U5.51@1257.56,802.84
NetR68_1: R68.1 U5.52 | length 978.2
  Layer 1 - Top Layer w10.1: R68.1@862.4,1521.1 862.4,1054.3 1002.8,913.9 1181.1,913.9 v2(1210,885)
  Layer 4 - Bottom Layer w10.1: v2(1210,885) 1237.88,857.12 U5.52@1237.88,802.84
NetR69_1: R69.1 U5.3 | length 472
  Layer 1 - Top Layer w10.1: v2(803.2,1443.4) 803.2,1519.3 R69.1@805,1521.1
  Layer 4 - Bottom Layer w10.1: v2(803.2,1443.4) 1061.6,1443.4 1119.77,1385.23 U5.3@1119.77,1332.36
NetR70_1: R70.1 U5.4 | length 583.3
  Layer 1 - Top Layer w10.1: v2(749,1438.1) 749,1520.1 R70.1@750,1521.1
  Layer 4 - Bottom Layer w10.1: v2(749,1438.1) 776.5,1465.6 1079.4,1465.6 1139.45,1405.55 U5.4@1139.45,1332.36
NetR122_2: R122.2 U6.5 | length 55.7
  Layer 1 - Top Layer w10.1: R122.2@1555,3671.5 1556.89,3673.39 U6.5@1609.88,3673.39
NetR123_2: R123.2 U7.4 | length 60.6
  Layer 1 - Top Layer w10.1: U7.4@1792.09,3226 1807.99,3241.9 R123.2@1807.99,3280
NetR124_1: R124.1 R125.2 U7.2 | length 114.2
  Layer 1 - Top Layer w10.1: U7.2@1766.5,3149.22 1766.5,3116.23 R124.1@1781.5,3101.23 R125.2@1841.5,3101.23
OE0#: JP5.2 R14.1 R31.2 U1.11 | length 2637.4
  Layer 1 - Top Layer w7.87: v2@1875,1679.13 1885.57,1689.7 1885.57,1707.13 1897.58,1719.13 U1.11@1932.87,1719.13
  Layer 1 - Top Layer w10.1: R14.1@1832.87,1664.13 1860,1664.13 v2@1875,1679.13
  Layer 3 - PWR w10.1: JP5.2@1662.6,2782.4 1742.8,2782.4 1960.1,2565.1 1960.1,2429 2034.2,2354.9 2079.2,2354.9 2106.3,2327.8 2106.3,2235.2 2201.3,2140.2 2331.4,2140.2 2462.26,2009.34 2462.26,1754.36 2375.95,1668.05 2168.55,1668.05 2128.4,1627.9 2128.4,1533 2100.6,1505.2 1917,1505.2 1874.88,1547.32 v2(1874.88,1679.25)
  Layer 4 - Bottom Layer w10.1: R31.2@1562.6,2782.4 JP5.2@1662.6,2782.4
OE0#DB803: JP3.2 R27.2 U1.12 | length 2937.2
  Layer 1 - Top Layer w7.87: v2@1900,1650 1900,1683.31 U1.12@1920.08,1703.39
  Layer 4 - Bottom Layer w10.1: R27.2@150,2823.25 JP3.2@257.6,2823.25 345,2735.85 345,1895 727.3,1512.7 1195.5,1512.7 1343.6,1660.8 1442.8,1660.8 1483,1620.6 1663.38,1620.6 1692.9,1650.12 v2(1899.88,1650.12)
OE1#: R32.2 S1.1 U1.18 | length 2792.4
  Layer 1 - Top Layer w7.87: U1.18@2042.13,1672.87 2042.13,1612.87 2069,1586 2069,1517.4 2102.6,1483.8 v2(2102.6,1414.8)
  Layer 1 - Top Layer w10.1: v2(659,2218.5) 659,2259.2 670.51,2270.71 S1.1@710,2270.71
  Layer 3 - PWR w10.1: v2(659,2218.5) 695.7,2181.8 695.7,1604.4 891.1,1409 1198.8,1409 1258.2,1468.4 1535.6,1468.4 1706.47,1297.53 2059.97,1297.53 2116.6,1354.15 2116.6,1400.8 v2(2102.6,1414.8)
  Layer 4 - Bottom Layer w10.1: v2(659,2218.5) 659,2184.8 687.3,2156.5 R32.2@710,2156.5
OE2#: R35.2 S1.2 U1.23 | length 2703.7
  Layer 1 - Top Layer w7.87: U1.23@2120.87,1672.87 2120.87,1639.23 2155.1,1605 v2(2204.8,1605)
  Layer 1 - Top Layer w10.1: v2(810,2202.68) S1.2@810,2270.71
  Layer 3 - PWR w10.1: v2(810,2202.68) 892.68,2120 1235.4,2120 1277.7,2162.3 1458.7,2162.3 1476,2179.6 1568.4,2179.6 1613.5,2134.5 1613.5,1434.1 1727.69,1319.91 1993.91,1319.91 2044.5,1370.5 2044.5,1410.7 2084.8,1451 2118.4,1451 2138.3,1431.1 2166.6,1431.1 2204.8,1469.3 v2(2204.8,1605)
  Layer 4 - Bottom Layer w10.1: R35.2@810,2156.5 v2(810,2202.68)
OE3#: R37.2 S1.3 U1.24 | length 2511.2
  Layer 1 - Top Layer w7.87: U1.24@2136.61,1660.08 2136.61,1648.39 2142.5,1642.5 v2(2203.4,1642.5)
  Layer 1 - Top Layer w10.1: v2(910,2202.68) S1.3@910,2270.71
  Layer 3 - PWR w10.1: v2(910,2202.68) 969.78,2142.9 1205.4,2142.9 1297.7,2235.2 1541.4,2235.2 1631.4,2145.2 1631.4,1453.5 1741.05,1343.85 1869.25,1343.85 1935.5,1410.1 1996.1,1410.1 2069.9,1483.9 2124,1483.9 2147.8,1507.7 2147.8,1612.8 2177.5,1642.5 v2(2203.4,1642.5)
  Layer 4 - Bottom Layer w10.1: R37.2@910,2156.5 v2(910,2202.68)
OE4#: R39.2 S1.4 U1.30 | length 3089.7
  Layer 1 - Top Layer w7.87: U1.30@2167.13,1782.13 2232.13,1782.13 2235,1785 2353.1,1785 2363.1,1795 v2(2380,1795)
  Layer 1 - Top Layer w10.1: v2(1010,2202.68) S1.4@1010,2270.71
  Layer 3 - PWR w10.1: v2(1010,2202.68) 1042.58,2170.1 1128.7,2170.1 1230.4,2271.8 1529,2271.8 1652.9,2147.9 1652.9,1470.6 1711.3,1412.2 1802.2,1412.2 1845.8,1455.8 1845.8,1692.7 1858.7,1705.6 1910.2,1705.6 1934.1,1681.7 1934.1,1553.5 1959.6,1528.01 2076.01,1528.01 2106.5,1558.5 2106.5,1636.4 2155.2,1685.1 2293.5,1685.1 2380,1771.6 v2(2380,1795)
  Layer 4 - Bottom Layer w10.1: R39.2@1010,2156.5 v2(1010,2202.68)
OE5#: R41.2 S1.5 U1.31 | length 2150.2
  Layer 1 - Top Layer w7.87: U1.31@2167.13,1797.87 2347.27,1797.87 2373.2,1823.8 2396.2,1823.8 v2(2410,1810)
  Layer 1 - Top Layer w10.1: v2(1110,2202.68) S1.5@1110,2270.71
  Layer 3 - PWR w10.1: v2(1110,2202.68) 1110,2376.8 1155.6,2422.4 1712.7,2422.4 1966.2,2168.9 2063.4,2168.9 2176.85,2055.45 2215.65,2055.45 2294.45,1976.65 2294.45,1925.55 v2(2410,1810)
  Layer 4 - Bottom Layer w10.1: R41.2@1110,2156.5 v2(1110,2202.68)
OE6#: R43.2 S1.6 U1.37 | length 1352.5
  Layer 1 - Top Layer w7.87: U1.37@2136.61,1907.13 2136.61,1921.61 2174.8,1959.8 v2(2174.8,2014.5)
  Layer 1 - Top Layer w10.1: v2(1210,2202.68) S1.6@1210,2270.71
  Layer 4 - Bottom Layer w10.1: R43.2@1210,2156.5 v2(1210,2202.68) 1297.32,2290 1899.3,2290 v2(2174.8,2014.5)
OE7#: R45.2 S1.7 U1.41 | length 1078.6
  Layer 1 - Top Layer w7.87: v2(2007,2041.3) 2055.2,1993.1 2055.2,1978.2 2073.62,1959.78 U1.41@2073.62,1907.54
  Layer 1 - Top Layer w10.1: v2(1310,2202.68) S1.7@1310,2270.71
  Layer 4 - Bottom Layer w10.1: R45.2@1310,2156.5 v2(1310,2202.68) 1357.32,2250 1798.3,2250 v2(2007,2041.3)
P3V3: JP6.2 L1.1 R2.2 R3.2 R24.2 R25.2 R30.2 R33.1 R36.1 R38.1 R40.1 R42.1 R44.2 R46.2 R48.2 R127.2 | length 431.7
  Layer 4 - Bottom Layer w20: R25.2@137.24,2740 v2(170.45,2740) ; v2(257.6,2560.19) R24.2@257.6,2593.41 ; v2(419.29,2300.57) R3.2@419.29,2333.78 ; R2.2@470.1,2770.49 v2(470.1,2803.7) ; R33.1@710,2778.62 v2(710,2811.83) ; R36.1@810,2778.62 v2(810,2811.83) ; R38.1@910,2778.62 v2(910,2811.83) ; R40.1@1010,2778.62 v2(1010,2811.83) ; R42.1@1110,2778.62 v2(1110,2811.83) ; R44.2@1210,2778.62 v2(1210,2811.83) ; R46.2@1310,2778.62 v2(1310,2811.83) ; R48.2@1410,2778.62 v2(1410,2811.83) ; v2(1557.91,2601.95) R30.2@1557.91,2635.16
P3V3_R: JP7.2 L2.1 R126.2
PUR: R53.1 R55.2 S2.1 S2.2 U5.63 | length 1453.8
  Layer 1 - Top Layer w20: 453,776.5 467.73,791.23 R53.1@500.92,791.23 540,791.23
  Layer 1 - Top Layer w30: S2.1@107.64,568.33 S2.2@465.91,568.33 R55.2@546.78,568.33 546.78,604.12 440.4,710.5 440.4,763.9 453,776.5 ; 540,791.23 986.23,791.23 v2(1045,850)
  Layer 4 - Bottom Layer w10.1: U5.63@1002.64,919.96 1044.9,919.96
  Layer 4 - Bottom Layer w15: 1044.9,919.96 1055,919.96 1065,909.96 1065,870 v2(1045,850)
SADR0: JP1.2 R17.1 | length 2388.9
  Layer 1 - Top Layer w10.1: v2(1526.77,1693.77) R17.1@1571.88,1693.77
  Layer 4 - Bottom Layer w10.1: JP1.2@562.6,2823.25 615,2770.85 615,2356.8 456.2,2198 456.2,1826.51 733.61,1549.1 1159.3,1549.1 1321.1,1710.9 1509.63,1710.9 v2(1526.77,1693.77)
SADR1: JP2.2 U1.8 | length 2648.3
  Layer 1 - Top Layer w8: v2(1895,1758.44) 1902.93,1766.38 U1.8@1932.87,1766.38
  Layer 4 - Bottom Layer w10.1: JP2.2@419.29,2565 503.4,2480.89 503.4,2322.8 409.7,2229.1 409.7,1851.65 728.25,1533.1 1173.6,1533.1 1327.2,1686.7 1471.4,1686.7 1506.8,1651.3 1633,1651.3 1655,1673.3 1655,1761.5 1686.4,1792.9 1860.55,1792.9 v2(1895,1758.44)
SCL: J6.12 R21.1 R54.1 R63.1 R66.2 | length 5686.9
  Layer 1 - Top Layer w10.1: R66.2@972.4,1584.09 R63.1@972.4,1651.1 v2(934.2,1651.1) 730.4,1651.1 713.3,1634 713.3,1089.2 911.45,891.05 1118.05,891.05 1169.1,840 1238.54,840 R54.1@1277.01,878.46
  Layer 3 - PWR w10.1: v2(934.2,1651.1) 868.55,1716.75 768.35,1716.75 716.8,1768.3 716.8,2219.2 979.2,2481.6 1487.6,2481.6 1589,2583 1589,2927.7 1700.24,3038.94 1700.24,3328.86 1329.1,3700 1062.2,3700 970.2,3608 970.2,3396.1 1068.8,3297.5 1068.8,3143.6 J6.12@1017.6,3092.4
  Layer 4 - Bottom Layer w10.1: R21.1@1017.6,2997.56 J6.12@1017.6,3092.4
SDA: J6.11 R22.1 R62.1 R65.2 | length 4316.6
  Layer 1 - Top Layer w10.1: R65.2@1027.4,1584.09 R62.1@1027.4,1651.1 v2(1065.6,1651.1)
  Layer 3 - PWR w10.1: J6.11@1017.6,3192.4 1017.6,3316.6 947.5,3386.7 947.5,3617.4 1052.8,3722.7 1338.5,3722.7 1722.94,3338.26 1722.94,3029.54 1611.7,2918.3 1611.7,2573.6 1497,2458.9 988.6,2458.9 752.6,2222.9 752.6,2028 818,1962.6 818,1898.7 834.8,1881.9 881.5,1881.9 900.8,1862.6 900.8,1815.9 v2(1065.6,1651.1)
  Layer 4 - Bottom Layer w10.1: J6.11@1017.6,3192.4 1065,3145 1065,3075 1115,3025 R22.1@1115,2997.56
SMBCLK: C14.1 R21.2 U1.7 | length 2059.6
  Layer 1 - Top Layer w7.87: v2@1725,1725 1782.13,1782.13 U1.7@1932.87,1782.13
  Layer 3 - PWR w10.1: v2(1173.4,2358.1) 1205.6,2390.3 1573.7,2390.3 1736.9,2227.1 1736.9,1737.14 v2(1724.88,1725.12)
  Layer 4 - Bottom Layer w10.1: R21.2@1017.6,2942.44 C14.1@1065,2942.44 1065,2466.5 v2(1173.4,2358.1)
SMBDAT: C13.1 R22.2 U1.6 | length 1957.7
  Layer 1 - Top Layer w7.87: v2@1710,1750 1757.87,1797.87 U1.6@1932.87,1797.87
  Layer 3 - PWR w10.1: v2(1304.9,2358.3) 1557.4,2358.3 1709.88,2205.82 v2(1709.88,1750.12)
  Layer 4 - Bottom Layer w10.1: R22.2@1115,2942.44 C13.1@1165,2942.44 1260.66,2942.44 1356.8,2846.3 1356.8,2410.2 v2(1304.9,2358.3)
SMBWRTLOCK: JP4.2 U1.46 | length 3162.9
  Layer 1 - Top Layer w7.87: v2(1970,1965) 1994.88,1940.12 U1.46@1994.88,1907.13
  Layer 4 - Bottom Layer w10.1: JP4.2@90,2565 184.1,2565 265,2484.1 265,1880.9 659,1486.9 1205.9,1486.9 1355.9,1636.9 1424.9,1636.9 1470.9,1590.9 1660.8,1590.9 1689.9,1620 1930,1620 1950,1640 1950,1945 v2(1970,1965)
U2A_3V3: C18.1 C19.1 C30.1 C31.1 C32.1 R51.2 R62.2 R63.2 R71.2 R72.2 U2.1 U3.5 U5.11 U5.18 U5.50 | length 341.9
  Layer 1 - Top Layer w15: R51.2@1458.9,717.6 1480,738.7 v2(1480,765)
  Layer 4 - Bottom Layer w10.1: v2(1267.87,757.87) 1277.25,767.25 U5.50@1277.25,802.84 ; U5.11@1277.25,1332.36 v2(1277.25,1382.25) ; U5.18@1415.04,1332.36 v2(1415.04,1382.25)
  Layer 4 - Bottom Layer w15: C32.1@1258.5,715 1258.5,748.5 v2(1267.87,757.87) ; v2(1277.25,1382.25) C30.1@1277.25,1427.44 ; v2(1415.04,1382.25) C31.1@1415.04,1427.44
  other v2: 1398.4,1022.1 1288.8,1034 1181.5,1069.7 571.3,1306.8 1329,1382.25
USB_D_N: J5.2 R50.1 U4.1 | length 390.3
  Layer 1 - Top Layer w10.1: J5.2@162.4,916.81 441.79,916.81 R50.1@453.68,928.7 453.68,951.32 445,960 v2(420,960)
  Layer 4 - Bottom Layer w10.1: U4.1@402.6,932.98 402.6,942.6 v2(420,960)
USB_D_P: J5.3 R52.1 U4.4 | length 410.1
  Layer 1 - Top Layer w10.1: J5.3@162.4,891.22 448.73,891.22 R52.1@453.68,886.27 453.68,868.68 445,860 v2(400,860)
  Layer 4 - Bottom Layer w10.1: U4.4@379.97,893.61 379.97,883.98 400,863.95 v2(400,860)
USB_GND: C24.2 J5.6 J5.7 J5.8 J5.9 J5.10 J5.11 R57.1
VDD: C1.1 C2.1 C3.1 C4.1 C5.1 C6.1 C7.1 C8.1 C12.1 L1.2 R6.1 R14.2 TP2.1 U1.15 U1.19 U1.27 U1.34 U1.38 U1.42 U1.44 | length 772.4
  Layer 1 - Top Layer w7.87: v2(1980.5,1560.3) 1980.5,1580.89 1994.57,1594.95 1994.57,1672.56 U1.15@1994.88,1672.87 ; v2(2002.2,1964.8) 2026.38,1940.62 U1.44@2026.38,1907.13 ; v2(2022.5,1992.6) 2022.5,1975.3 2057.87,1939.93 U1.42@2057.87,1907.13 ; U1.19@2057.87,1672.87 2057.87,1649.53 2066.1,1641.3 v2(2066.1,1625.9) ; U1.38@2120.87,1907.13 2120.87,1955.57 v2(2131.6,1966.3) ; U1.27@2167.13,1734.88 2247.52,1734.88 2261.3,1721.1 v2(2279.1,1721.1)
  Layer 1 - Top Layer w8: U1.34@2167.13,1845.12 2235.12,1845.12 v2(2250,1860)
  Layer 1 - Top Layer w30: v2(1769.88,1568.88) R14.2@1769.88,1664.13 1769.88,1693.38 v2(1774.88,1698.38)
  Layer 4 - Bottom Layer w30: v2(1774.88,1698.38) R6.1@1774.88,1732.13
VDDR: C9.1 C10.1 C11.1 C15.1 R1.2 R7.1 R8.1 R20.2 R23.2 | length 3234.1
  Layer 1 - Top Layer w20: v2(1532.26,2211.02) C15.1@1577.87,2211.02
  Layer 1 - Top Layer w25: v2(1764.8,1977.5) R7.1@1764.8,2012.29
  Layer 1 - Top Layer w30: R20.2@513.5,1668.84 v2(513.5,2037.24) R8.1@513.5,2082.85 ; v2(1534.26,2151.02) R23.2@1579.88,2151.02
  Layer 3 - PWR w25: v2@863,2087.2 1270.8,2087.2 1308.4,2124.8 1508.04,2124.8 v2(1534.26,2151.02)
  Layer 4 - Bottom Layer w23: v2(513.5,2037.24) 513.5,2185.1 602.05,2273.65 662.1,2273.65 662.1,2899.4 662.1,2944 567.62,3038.48 567.62,3281.95 537.4,3312.17 C9.1@537.4,3408.02 R1.2@597.4,3408.02 ; 641.8,2273.4 662.1,2293.7 682.4,2273.4 ; 662.1,2273.4 817.1,2273.4 862.7,2227.8 v2(862.7,2087.5)
VIN1: C39.1 C40.1 C41.1 J3.1 JP6.1 R121.2 TP3.1
  other v2: 1385.02,3758.69 1329.34,3759.57 1228.82,3808.6 1284.5,3808.6 1329.64,3808.6 1385.32,3808.6 1230.22,3859.29 1285.9,3859.29 1329.94,3859.29 1385.62,3859.29
VIN2: C46.1 C47.1 C48.1 J4.1 JP7.1 TP5.1
  other v2: 806,3644.8 750.32,3645.68 806.3,3695.1 750.62,3695.98 806.6,3745.4 750.92,3746.28 806.9,3795.7 751.22,3796.58 807.2,3846 751.52,3846.88
VUSB: C22.1 S2.3 S2.4 U5.66 | length 1464.1
  Layer 1 - Top Layer w30: S2.3@107.64,391.17 C22.1@546.78,391.17 581.07,391.17 644.4,454.5 644.4,534.2 774.4,664.2 957.5,664.2 1100.2,806.9 v2(1100.2,864)
  Layer 4 - Bottom Layer w10.1: U5.66@1002.64,979.02 1044.83,979.02 1045.2,979.38 1070.32,979.38 1100.2,949.5 v2(1100.2,864)
pads on no net: D3.2 FID1.1 FID2.1 FID3.1 FID4.1 FID5.1 FID6.1 H1.0 H2.0 H3.0 H4.0 J5.4 J6.1 J6.2 J6.7 J6.8 J6.9 J6.10 J6.16 J6.21 J6.22 J6.24 J6.26 J6.28 J6.30 SH1.0 SH2.0 SH3.0 SH4.0 U1.9 U1.20 U1.43 U1.45 U1.47 U1.48 U2.2 U2.5 U4.2 U4.5 U5.1 U5.2 U5.5 U5.6 U5.7 U5.8 U5.9 U5.10 U5.12 U5.13 U5.16 U5.17 U5.22 U5.24 U5.25 U5.26 U5.27 U5.28 U5.30 U5.31 U5.32 U5.34 U5.35 U5.36 U5.37 U5.38 U5.39 U5.40 U5.41 U5.43 U5.44 U5.48 U5.53 U5.54 U5.55 U5.56 U5.71 U5.72 U5.73 U5.74 U5.75 U5.77 U5.78 U5.79 U5.80 U6.2 U6.6 U6.7 U7.5 U7.7@1748.78,3187.61 U7.7@1784.21,3187.61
